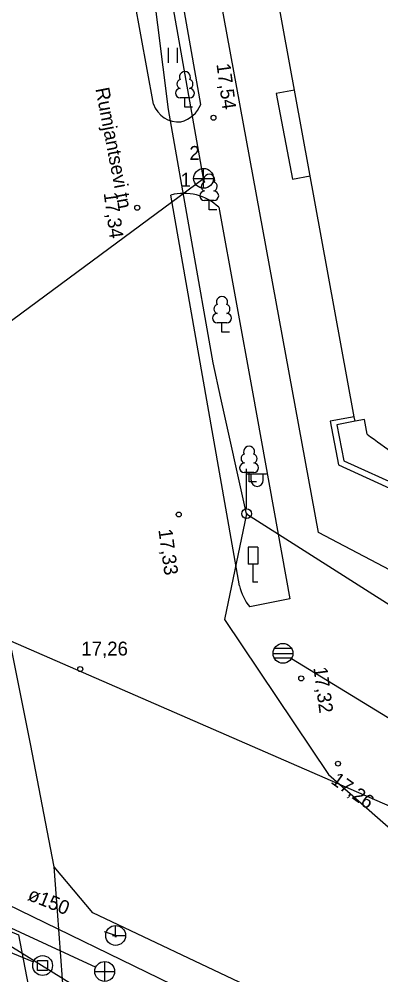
# Model space of a CAD drawing. Extents: x 713540 to 713867, y 6589774 to 6590061.
# Drawn here: x 713682.55 to 713700.77, y 6589915.75 to 6589963.85 of the extents above; entities that cross this region are included whole.
import ezdxf

# ---------------------------------------------------------------- set-up
doc = ezdxf.new("R2010")
doc.units = 0
for name, color, linetype in [('DKAEV', 7, 'Continuous'), ('HALJASTUS', 7, 'Continuous'), ('HOONE', 7, 'Continuous'), ('KKAEV', 7, 'Continuous'), ('KORGUS', 7, 'Continuous'), ('KPKAABEL', 7, 'Continuous'), ('KTRASS', 7, 'Continuous'), ('LIIKLUS', 7, 'Continuous'), ('MPKAABEL', 7, 'Continuous'), ('POST', 7, 'Continuous'), ('PUU', 7, 'Continuous'), ('RAJATIS', 7, 'Continuous'), ('SITRASS', 7, 'Continuous'), ('SKKAEV', 7, 'Continuous'), ('SKTRASS', 7, 'Continuous'), ('TEE', 7, 'Continuous'), ('TORU NR', 7, 'Continuous'), ('VTRASS', 7, 'Continuous'), ('По умолчанию', 7, 'Continuous'), ('Слой 1', 7, 'Continuous')]:
    doc.layers.add(name, color=color, linetype=linetype)

msp = doc.modelspace()

# ---------------------------------------------------------------- linework, layer by layer
at = {"layer": 'DKAEV'}
for p, q in [((713683.482, 6589915.968), (713683.482, 6589916.468)), ((713683.482, 6589916.468), (713683.982, 6589916.468)), ((713683.982, 6589916.468), (713683.982, 6589915.968)), ((713683.982, 6589915.968), (713683.482, 6589915.968))]:
    msp.add_line(p, q, dxfattribs=at)
msp.add_circle((713683.732, 6589916.218), 0.5, dxfattribs=at)
at = {"layer": 'HALJASTUS'}
for p, q in [((713690.053, 6589962.414), (713690.053, 6589961.653)), ((713690.508, 6589962.414), (713690.508, 6589961.653))]:
    msp.add_line(p, q, dxfattribs=at)
at = {"layer": 'HOONE'}
for points in [[(713700.081, 6589942.962), (713699.945, 6589943.703), (713699.469, 6589943.616), (713699.43, 6589943.831), (713694.186, 6589972.51), (713708.231, 6589975.063), (713712.15, 6589954.52), (713714.85, 6589952.78), (713720.42, 6589962.79), (713724.48, 6589971.41), (713726.078, 6589970.623), (713726.102, 6589970.646), (713737.433, 6589964.699), (713721.341, 6589934.036), (713720.864, 6589934.287), (713720.463, 6589933.523)], [(713696.422, 6589960.283), (713695.503, 6589960.115), (713696.315, 6589955.8), (713697.211, 6589955.964)], [(713699.43, 6589943.831), (713698.222, 6589943.61), (713698.634, 6589941.413), (713702.592, 6589939.613), (713703.037, 6589940.47)], [(713644.142, 6589932.53), (713676.393, 6589919.242), (713683.27, 6589916.408)]]:
    msp.add_lwpolyline(points, dxfattribs=at)
msp.add_arc((713784.999, 6590057.779), 142.808, 233.51375, 234.89164, dxfattribs=at)
at = {"layer": 'KKAEV'}
for p, q in [((713691.841, 6589955.337), (713691.841, 6589956.337)), ((713691.341, 6589955.837), (713692.341, 6589955.837)), ((713686.861, 6589915.419), (713686.861, 6589916.419)), ((713686.361, 6589915.919), (713687.361, 6589915.919))]:
    msp.add_line(p, q, dxfattribs=at)
for centre in [(713691.841, 6589955.837), (713686.861, 6589915.919)]:
    msp.add_circle(centre, 0.5, dxfattribs=at)
at = {"layer": 'KORGUS'}
for centre in [(713692.34, 6589958.89), (713688.5, 6589954.36), (713690.59, 6589938.92), (713685.63, 6589931.14), (713696.76, 6589930.67), (713698.61, 6589926.38)]:
    msp.add_circle(centre, 0.125, dxfattribs=at)
at = {"layer": 'KPKAABEL'}
msp.add_lwpolyline([(713539.965, 6589980.838), (713552.788, 6589975.379), (713567.02, 6589969.273), (713582.283, 6589962.777), (713617.601, 6589947.676), (713629.099, 6589942.656), (713644.667, 6589936.214), (713656.147, 6589931.294), (713657.314, 6589931.177), (713661.667, 6589932.013), (713662.753, 6589932.107), (713664.149, 6589932.005), (713666.08, 6589931.349), (713666.349, 6589931.058), (713668.526, 6589927.166), (713675.247, 6589923.087), (713676.674, 6589921.464), (713677.591, 6589920.422), (713678.393, 6589919.51), (713687.845, 6589913.651)], dxfattribs=at)
at = {"layer": 'KTRASS'}
for q in [(713691.841, 6589955.837), (713719.763, 6589916.166)]:
    msp.add_line((713668.395, 6589938.534), q, dxfattribs=at)
for points in [[(713665.334, 6589925.861), (713677.438, 6589920.271), (713686.407, 6589916.129)], [(713687.41, 6589917.73), (713686.856, 6589917.919)], [(713687.41, 6589917.73), (713687.422, 6589917.647)]]:
    msp.add_lwpolyline(points, dxfattribs=at)
at = {"layer": 'LIIKLUS'}
for points in [[(713694.079, 6589937.268), (713694.079, 6589936.418)], [(713694.579, 6589937.268), (713694.079, 6589937.268)], [(713694.579, 6589937.268), (713694.579, 6589936.418)], [(713694.579, 6589936.418), (713694.079, 6589936.418)], [(713694.329, 6589936.418), (713694.329, 6589935.518)], [(713694.579, 6589935.518), (713694.329, 6589935.518)]]:
    msp.add_lwpolyline(points, dxfattribs=at)
at = {"layer": 'MPKAABEL'}
for points in [[(713692.718, 6589944.775), (713692.321, 6589946.558), (713690.066, 6589959.298), (713688.999, 6589967.843), (713683.646, 6589996.839), (713676.43, 6590037.515), (713672.265, 6590060.636)], [(713694.011, 6589938.961), (713692.718, 6589944.775)], [(713694.011, 6589938.961), (713692.89, 6589933.64), (713698.13, 6589925.84), (713701.56, 6589922.83), (713707.37, 6589919), (713707.983, 6589913.318), (713708.27, 6589910.66), (713700.37, 6589905.55), (713699.23, 6589901.46), (713701.24, 6589889.8), (713704.212, 6589873.404), (713706.92, 6589858.46), (713712.25, 6589828.58), (713717.93, 6589797.45), (713721.28, 6589780.69), (713722.515, 6589774.068)], [(713694.011, 6589938.961), (713720.287, 6589922.261), (713729.28, 6589921.07), (713735.396, 6589911.684), (713736.91, 6589909.36), (713749.796, 6589902.534), (713750.086, 6589902.788), (713778.179, 6589889.116), (713778.272, 6589888.686), (713778.52, 6589888.95), (713802.27, 6589877.73), (713802.558, 6589876.915), (713802.91, 6589877.43), (713827.719, 6589864.835), (713849.02, 6589854.61), (713849.184, 6589854.353), (713849.72, 6589854.26), (713866.671, 6589846.028)]]:
    msp.add_lwpolyline(points, dxfattribs=at)
at = {"layer": 'POST'}
for p, q in [((713694.011, 6589939.211), (713694.011, 6589941.211)), ((713694.011, 6589940.961), (713695.011, 6589940.961)), ((713694.237, 6589940.641), (713694.237, 6589940.961)), ((713694.85, 6589940.641), (713694.85, 6589940.961))]:
    msp.add_line(p, q, dxfattribs=at)
for radius in [0.25, 0.0234]:
    msp.add_circle((713694.011, 6589938.961), radius, dxfattribs=at)
msp.add_arc((713694.544, 6589940.641), 0.306, 180, 0, dxfattribs=at)
at = {"layer": 'PUU'}
for p, q in [((713691.142, 6589959.894), (713690.662, 6589959.894)), ((713690.902, 6589959.419), (713690.902, 6589959.894)), ((713691.282, 6589959.419), (713690.902, 6589959.419)), ((713692.366, 6589954.729), (713691.886, 6589954.729)), ((713692.126, 6589954.254), (713692.126, 6589954.729)), ((713692.506, 6589954.254), (713692.126, 6589954.254)), ((713693.007, 6589948.569), (713692.527, 6589948.569)), ((713692.767, 6589948.094), (713692.767, 6589948.569)), ((713693.147, 6589948.094), (713692.767, 6589948.094)), ((713694.372, 6589941.037), (713693.892, 6589941.037)), ((713694.132, 6589940.562), (713694.132, 6589941.037)), ((713694.512, 6589940.562), (713694.132, 6589940.562))]:
    msp.add_line(p, q, dxfattribs=at)
for centre, radius, start, end in [((713690.902, 6589960.939), 0.277, 332.5799, 207.4201), ((713690.732, 6589960.591), 0.233, 109.0217, 253.1415), ((713691.072, 6589960.591), 0.233, 286.8508, 70.9859), ((713690.664, 6589960.131), 0.238, 90.0016, 269.3953), ((713691.139, 6589960.131), 0.238, 270.6047, 89.9984), ((713692.126, 6589955.774), 0.277, 332.5799, 207.4201), ((713691.956, 6589955.426), 0.233, 109.0217, 253.1415), ((713692.296, 6589955.426), 0.233, 286.8508, 70.9859), ((713691.888, 6589954.966), 0.238, 90.0016, 269.3953), ((713692.363, 6589954.966), 0.238, 270.6047, 89.9984), ((713692.767, 6589949.614), 0.277, 332.5799, 207.4201), ((713692.53, 6589948.807), 0.238, 90.0016, 269.3953), ((713692.597, 6589949.267), 0.233, 109.0217, 253.1415), ((713692.937, 6589949.267), 0.233, 286.8508, 70.9859), ((713693.005, 6589948.807), 0.238, 270.6047, 89.9984), ((713694.132, 6589942.082), 0.277, 332.5799, 207.4201), ((713693.962, 6589941.735), 0.233, 109.0217, 253.1415), ((713694.302, 6589941.735), 0.233, 286.8508, 70.9859), ((713693.895, 6589941.275), 0.238, 90.0016, 269.3953), ((713694.37, 6589941.275), 0.238, 270.6047, 89.9984)]:
    msp.add_arc(centre, radius, start, end, dxfattribs=at)
at = {"layer": 'RAJATIS'}
for p, q in [((713699.469, 6589943.616), (713698.561, 6589943.439)), ((713698.561, 6589943.439), (713698.9, 6589941.622)), ((713698.9, 6589941.622), (713702.457, 6589940.004))]:
    msp.add_line(p, q, dxfattribs=at)
at = {"layer": 'SITRASS'}
msp.add_lwpolyline([(713680.008, 6589920.248), (713692.16, 6589914.332), (713701.195, 6589909.935), (713709.36, 6589905.96), (713721.89, 6589899.976)], dxfattribs=at)
at = {"layer": 'SKKAEV'}
for p, q in [((713695.339, 6589931.93), (713696.339, 6589931.93)), ((713696.269, 6589932.18), (713695.409, 6589932.18)), ((713696.269, 6589931.68), (713695.409, 6589931.68))]:
    msp.add_line(p, q, dxfattribs=at)
msp.add_circle((713695.839, 6589931.93), 0.5, dxfattribs=at)
at = {"layer": 'SKTRASS'}
msp.add_lwpolyline([(713696.266, 6589931.669), (713716.737, 6589919.178)], dxfattribs=at)
at = {"layer": 'TEE'}
msp.add_line((713691.841, 6589955.837), (713683.799, 6590000.987), dxfattribs=at)
for points in [[(713691.7, 6589959.557), (713688.046, 6589980.323), (713678.974, 6590031.096)], [(713689.318, 6589959.578), (713688.035, 6589966.571), (713686.357, 6589979.631), (713686.045, 6589981.554), (713684.475, 6589986.323), (713676.697, 6590028.946)], [(713693.647, 6589935.332), (713692.005, 6589944.678), (713690.192, 6589954.999)], [(713692.604, 6589954.386), (713694.314, 6589944.992), (713696.191, 6589934.673)], [(713696.191, 6589934.673), (713694.165, 6589934.27)]]:
    msp.add_lwpolyline(points, dxfattribs=at)
for centre, radius, start, end in [((713690.569, 6589960.004), 1.321, 198.815, 275.7853), ((713690.362, 6589960.088), 1.439, 283.6678, 338.3512), ((713690.848, 6589952.524), 2.56, 46.6644, 104.8436), ((713690.848, 6589952.524), 2.56, 46.6644, 104.8436), ((713696.361, 6589935.998), 2.794, 193.7919, 218.1911)]:
    msp.add_arc(centre, radius, start, end, dxfattribs=at)
at = {"layer": 'VTRASS'}
for points in [[(713684.308, 6589921.181), (713683.129, 6589927.373), (713681.203, 6589936.836), (713678.244, 6589950.963), (713676.229, 6589960.85), (713673.946, 6589973.712), (713673.362, 6589976.754), (713673.233, 6589977.362), (713672.25, 6589983.027), (713670.156, 6589996.06), (713667.268, 6590011.807), (713664.478, 6590027.857), (713664.208, 6590029.493), (713663.195, 6590035.091), (713660.78, 6590048.281), (713658.62, 6590060.636)], [(713721.093, 6589902.329), (713720.528, 6589902.588), (713708.752, 6589908.105), (713703.079, 6589910.841), (713694.266, 6589915.073), (713686.266, 6589918.865), (713684.308, 6589921.181)], [(713708.725, 6589774.068), (713707.065, 6589783.601), (713705.018, 6589794.55), (713701.84, 6589812.321), (713699.235, 6589827.436), (713699.875, 6589827.579), (713696.888, 6589845.261), (713694.289, 6589860.829), (713691.539, 6589877.243), (713690.275, 6589883.906), (713690.135, 6589884.996), (713689.231, 6589889.843), (713687.737, 6589897.698), (713684.897, 6589913.25), (713684.491, 6589918.952), (713684.308, 6589921.181)]]:
    msp.add_lwpolyline(points, dxfattribs=at)
at = {"layer": 'По умолчанию'}
for p, q in [((713687.41, 6589917.653), (713687.41, 6589918.23)), ((713687.25, 6589917.73), (713687.91, 6589917.73))]:
    msp.add_line(p, q, dxfattribs=at)
msp.add_circle((713687.41, 6589917.73), 0.5, dxfattribs=at)
at = {"layer": 'Слой 1'}
for points in [[(713689.74, 6589981), (713702.78, 6589983.59), (713701.84, 6589988.96), (713713.13, 6589989.8), (713713.92, 6589985.29), (713742.5, 6589970.55), (713718.97, 6589926.81), (713697.63, 6589938.02)], [(713682.51, 6589917.77), (713690.33, 6589877.18), (713657.78, 6589870.72), (713657.67, 6589868.71), (713640.88, 6589865.96), (713635.67, 6589892.95), (713631.47, 6589895.07), (713633.95, 6589902.38), (713645.78, 6589933.24)]]:
    msp.add_lwpolyline(points, close=True, dxfattribs=at)

# ---------------------------------------------------------------- texts
at = {"layer": 'KORGUS'}
for s, rotation, p in [('17,54', 277.7119, (713692.487, 6589961.586)), ('17,34', 277.7119, (713686.807, 6589955.096)), ('17,33', 277.7119, (713689.563, 6589938.15)), ('17,32', 277.7119, (713697.371, 6589931.207)), ('17,26', 324.3171, (713698.208, 6589925.424))]:
    msp.add_text(s, height=0.7, rotation=rotation, dxfattribs=at).set_placement(p)
msp.add_text('17,26', height=0.7, dxfattribs=at).set_placement((713685.685, 6589931.82))
at = {"layer": 'TEE'}
msp.add_text('Rumjantsevi tn', height=0.7, rotation=280.9285, dxfattribs=at).set_placement((713686.389, 6589960.348))
at = {"layer": 'TORU NR'}
for s, p in [('2', (713691.125, 6589956.767)), ('1', (713690.685, 6589955.417))]:
    msp.add_text(s, height=0.7, dxfattribs=at).set_placement(p)
msp.add_text('ø150', height=0.7, rotation=338.2585, dxfattribs=at).set_placement((713682.929, 6589919.535))

doc.saveas('drawing.dxf')
